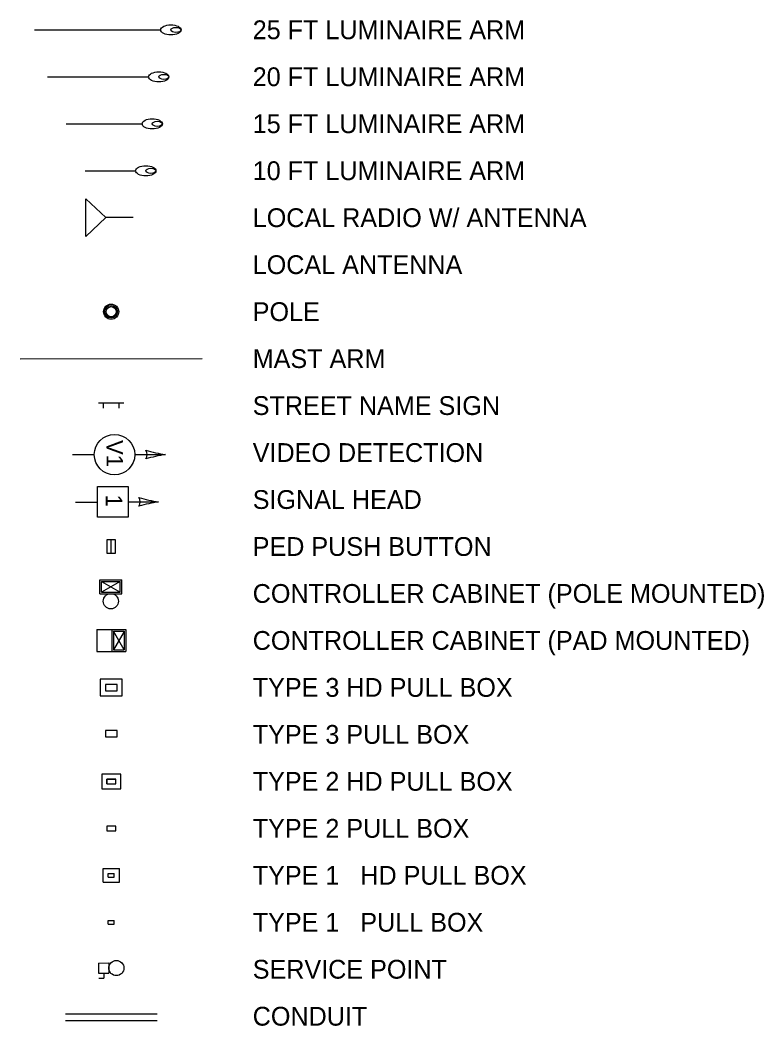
# Model space of a CAD drawing. Extents: x 994024 to 994914, y 1985815 to 1986420.
# Drawn here: x 994063.9 to 994211, y 1986220.6 to 1986419.7 of the extents above; entities that cross this region are included whole.
import ezdxf

# ---------------------------------------------------------------- set-up
doc = ezdxf.new("R2010")
doc.units = 0
for name, color, linetype in [('S_CROSS_DRAIN', 7, 'Continuous'), ('S_CURB', 7, 'Continuous'), ('S_DRIVEWAY', 7, 'Continuous'), ('S_ORTHO_IMAGE', 7, 'Continuous'), ('S_PARKING', 7, 'Continuous'), ('S_PAVEMENT_CROWN', 7, 'Continuous'), ('S_SHOULDER', 7, 'Continuous'), ('S_SIDEWALK', 7, 'Continuous'), ('S_WALL_ANNOT', 7, 'Continuous')]:
    doc.layers.add(name, color=color, linetype=linetype)

msp = doc.modelspace()

# ---------------------------------------------------------------- linework, layer by layer
at = {"layer": 'S_CROSS_DRAIN'}
for p, q in [((994084.36, 1986343.86), (994079.36, 1986343.86)), ((994080.36, 1986342.86), (994080.36, 1986343.86)), ((994083.36, 1986343.86), (994083.36, 1986342.86)), ((994084.36, 1986343.86), (994083.36, 1986343.86))]:
    msp.add_line(p, q, dxfattribs=at)
at = {"layer": 'S_CURB'}
msp.add_line((994063.85, 1986352.66), (994099.85, 1986352.67), dxfattribs=at)
for radius in [1.5, 1.25, 1]:
    msp.add_circle((994081.85, 1986361.97), radius, dxfattribs=at)
at = {"layer": 'S_DRIVEWAY'}
for p, q in [((994084.05, 1986289.19), (994079.72, 1986289.19)), ((994079.72, 1986289.19), (994079.72, 1986285.92)), ((994084.05, 1986285.92), (994084.05, 1986289.19)), ((994080.72, 1986288.19), (994080.72, 1986286.92)), ((994083.05, 1986288.19), (994080.72, 1986288.19)), ((994080.72, 1986286.92), (994083.05, 1986286.92)), ((994083.05, 1986286.92), (994083.05, 1986288.19)), ((994079.72, 1986285.92), (994084.05, 1986285.92)), ((994080.71, 1986279.07), (994080.72, 1986277.8)), ((994083.05, 1986279.07), (994080.71, 1986279.07)), ((994083.05, 1986277.8), (994083.05, 1986279.07)), ((994080.72, 1986277.8), (994083.05, 1986277.8)), ((994083.76, 1986270.42), (994080.01, 1986270.41)), ((994080.01, 1986270.41), (994080.01, 1986267.49)), ((994083.76, 1986267.5), (994083.76, 1986270.42)), ((994081.01, 1986268.5), (994081.01, 1986269.42)), ((994081.01, 1986269.42), (994082.76, 1986269.42)), ((994081.01, 1986269.42), (994081.01, 1986268.5)), ((994082.76, 1986269.42), (994081.01, 1986269.42)), ((994081.01, 1986268.5), (994082.76, 1986268.5)), ((994081.01, 1986268.5), (994082.76, 1986268.5)), ((994082.76, 1986268.5), (994082.76, 1986269.42)), ((994082.76, 1986268.5), (994082.76, 1986269.42)), ((994080.01, 1986267.49), (994083.76, 1986267.5)), ((994081.01, 1986260.12), (994081.02, 1986259.2)), ((994082.76, 1986260.12), (994081.01, 1986260.12)), ((994081.02, 1986259.2), (994082.77, 1986259.2)), ((994082.77, 1986259.2), (994082.76, 1986260.12))]:
    msp.add_line(p, q, dxfattribs=at)
msp.add_lwpolyline([(994081, 1986314.14), (994082.75, 1986314.14), (994082.75, 1986316.78), (994081.01, 1986316.78)], close=True, dxfattribs=at)
at = {"layer": 'S_PARKING'}
for p, q in [((994079.39, 1986233.01), (994081.39, 1986233.02)), ((994079.39, 1986233.01), (994079.39, 1986231.01)), ((994081.39, 1986233.02), (994081.39, 1986231.02)), ((994079.39, 1986231.01), (994081.39, 1986231.02)), ((994080.39, 1986231.01), (994080.4, 1986230.01)), ((994079.4, 1986230.01), (994080.4, 1986230.01)), ((994072.83, 1986222.95), (994090.96, 1986222.96)), ((994072.83, 1986221.63), (994090.96, 1986221.63))]:
    msp.add_line(p, q, dxfattribs=at)
msp.add_circle((994082.89, 1986232.02), 1.5, dxfattribs=at)
at = {"layer": 'S_PAVEMENT_CROWN'}
for p, q in [((994079.01, 1986299.02), (994084.75, 1986299.02)), ((994079.01, 1986299.02), (994079.01, 1986294.69)), ((994082.01, 1986299.02), (994082.01, 1986294.69)), ((994082.34, 1986298.69), (994082.34, 1986295.02)), ((994084.42, 1986295.02), (994082.34, 1986298.69)), ((994082.34, 1986298.69), (994084.42, 1986298.69)), ((994084.42, 1986298.67), (994082.34, 1986295.02)), ((994084.42, 1986298.69), (994084.42, 1986295.02)), ((994084.75, 1986299.02), (994084.75, 1986294.69)), ((994079.01, 1986294.69), (994084.75, 1986294.69)), ((994082.34, 1986295.02), (994084.42, 1986295.02))]:
    msp.add_line(p, q, dxfattribs=at)
at = {"layer": 'S_SHOULDER'}
for p, q in [((994066.68, 1986417.75), (994091.68, 1986417.76)), ((994069.28, 1986408.45), (994089.28, 1986408.46)), ((994072.99, 1986399.15), (994087.99, 1986399.16)), ((994076.71, 1986389.85), (994086.71, 1986389.86)), ((994076.84, 1986376.84), (994076.84, 1986384.34)), ((994076.84, 1986384.34), (994080.84, 1986380.59)), ((994080.84, 1986380.59), (994076.84, 1986376.84)), ((994086.19, 1986380.59), (994080.84, 1986380.59)), ((994079.63, 1986306.14), (994079.63, 1986308.88)), ((994079.63, 1986308.88), (994083.96, 1986308.88)), ((994079.96, 1986308.55), (994083.63, 1986308.55)), ((994079.96, 1986306.47), (994079.96, 1986308.55)), ((994083.63, 1986308.55), (994079.96, 1986306.47)), ((994079.98, 1986308.55), (994083.63, 1986306.47)), ((994083.63, 1986306.47), (994083.63, 1986308.55)), ((994083.96, 1986306.14), (994083.96, 1986308.88)), ((994079.96, 1986306.47), (994083.63, 1986306.47)), ((994079.63, 1986306.14), (994083.96, 1986306.14)), ((994080.3, 1986251.72), (994083.49, 1986251.72)), ((994080.3, 1986248.99), (994080.3, 1986251.72)), ((994081.3, 1986249.99), (994081.3, 1986250.72)), ((994081.3, 1986250.72), (994082.49, 1986250.72)), ((994082.49, 1986249.99), (994082.49, 1986250.72)), ((994083.49, 1986248.99), (994083.49, 1986251.72)), ((994080.3, 1986248.99), (994083.49, 1986248.99)), ((994081.3, 1986249.99), (994082.49, 1986249.99)), ((994081.3, 1986240.69), (994081.3, 1986241.42)), ((994081.3, 1986241.42), (994082.49, 1986241.42)), ((994081.3, 1986240.69), (994082.49, 1986240.69)), ((994082.49, 1986240.69), (994082.49, 1986241.42))]:
    msp.add_line(p, q, dxfattribs=at)
msp.add_circle((994081.8, 1986304.64), 1.5, dxfattribs=at)
for centre, major_axis in [((994093.68, 1986417.76), (2, 0)), ((994094.68, 1986417.76), (-1, 0)), ((994091.28, 1986408.46), (2, 0)), ((994092.28, 1986408.46), (-1, 0)), ((994089.99, 1986399.16), (2, 0)), ((994090.99, 1986399.16), (-1, 0)), ((994088.71, 1986389.86), (2, 0)), ((994089.71, 1986389.86), (-1, 0))]:
    msp.add_ellipse(centre, major_axis=major_axis, ratio=0.5, dxfattribs=at)
at = {"layer": 'S_SIDEWALK'}
for p, q in [((994074.2, 1986333.67), (994078.53, 1986333.67)), ((994086.53, 1986333.67), (994092.6, 1986333.68)), ((994074.8, 1986324.29), (994079.14, 1986324.29)), ((994085.21, 1986324.31), (994091.25, 1986324.32))]:
    msp.add_line(p, q, dxfattribs=at)
msp.add_lwpolyline([(994079.15, 1986321.27), (994079.14, 1986327.34), (994085.21, 1986327.34), (994085.21, 1986321.27)], close=True, dxfattribs=at)
msp.add_circle((994082.53, 1986333.67), 4, dxfattribs=at)
for centre, radius, start, end in [((994087.33, 1986333.67), 1.63, 328.1778, 31.8725), ((994097, 1986362.82), 29.47, 253.6787, 261.4168), ((994097.02, 1986304.54), 29.47, 98.6335, 106.3716), ((994085.98, 1986324.31), 1.63, 328.1778, 31.8725), ((994095.65, 1986353.46), 29.47, 253.6787, 261.4168), ((994095.67, 1986295.18), 29.47, 98.6335, 106.3716)]:
    msp.add_arc(centre, radius, start, end, dxfattribs=at)
at = {"layer": 'S_WALL_ANNOT'}
msp.add_lwpolyline([(994081.01, 1986316.78), (994081, 1986314.14), (994081.88, 1986314.14), (994081.88, 1986316.78)], close=True, dxfattribs=at)

# ---------------------------------------------------------------- texts
at = {"layer": 'S_ORTHO_IMAGE'}
for s, p in [('25 FT LUMINAIRE ARM', (994109.87, 1986415.92)), ('20 FT LUMINAIRE ARM', (994109.87, 1986406.62)), ('15 FT LUMINAIRE ARM', (994109.87, 1986397.32)), ('10 FT LUMINAIRE ARM', (994109.87, 1986388.02)), ('LOCAL RADIO W/ ANTENNA', (994109.87, 1986378.72)), ('LOCAL ANTENNA', (994109.87, 1986369.42)), ('POLE', (994109.87, 1986360.12)), ('MAST ARM', (994109.87, 1986350.82)), ('STREET NAME SIGN', (994109.87, 1986341.52)), ('VIDEO DETECTION', (994109.87, 1986332.22)), ('SIGNAL HEAD', (994109.87, 1986322.92)), ('PED PUSH BUTTON', (994109.87, 1986313.62)), ('CONTROLLER CABINET (POLE MOUNTED)', (994109.87, 1986304.32)), ('CONTROLLER CABINET (PAD MOUNTED)', (994109.87, 1986295.02)), ('TYPE 3 HD PULL BOX', (994109.87, 1986285.72)), ('TYPE 3 PULL BOX', (994109.87, 1986276.42)), ('TYPE 2 HD PULL BOX', (994109.87, 1986267.12)), ('TYPE 2 PULL BOX', (994109.87, 1986257.82)), ('TYPE 1   HD PULL BOX', (994109.87, 1986248.52)), ('TYPE 1   PULL BOX', (994109.87, 1986239.22)), ('SERVICE POINT', (994109.87, 1986229.92)), ('CONDUIT', (994109.87, 1986220.62))]:
    msp.add_text(s, height=3.72, dxfattribs=at).set_placement(p)
at = {"layer": 'S_SIDEWALK'}
for s, p in [('V1', (994080.94, 1986336.55)), ('1', (994080.8, 1986325.77))]:
    msp.add_text(s, height=3.25, rotation=270.0252, dxfattribs=at).set_placement(p)

doc.saveas('drawing.dxf')
